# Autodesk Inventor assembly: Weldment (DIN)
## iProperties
Length Units: 11269
Angle Units: 11283
Time Units: 11279
Mass Units: 11290
Length Display Precision: 3
Angle Display Precision: 2
Part Number: Weldment (DIN)
Document SubType Name: Weldment
Created: 2002-06
Designer: smithga
Created: 2002-08
Control State: 0
Master: False
Shininess: 64.0
Angle Units: 11279
Time Units: 11290
Mass Units: 11283
Compacted: True
Density: 0.0
Volumn: 0.0
Area: 0.0
PropertySet Name: Model Information
